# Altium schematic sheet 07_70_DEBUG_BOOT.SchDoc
size 289 x 396 mm
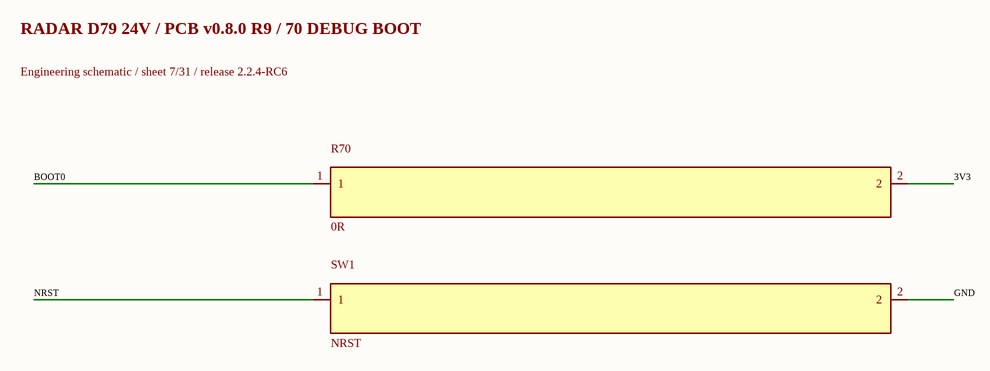
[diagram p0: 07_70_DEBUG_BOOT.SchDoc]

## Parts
R70  0R  [R_0603_1608Metric]
SW1  NRST  [ESwitch_TL3301_GullWing_6x6]

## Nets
3V3: R70.2
BOOT0: R70.1
GND: SW1.2
NRST: SW1.1

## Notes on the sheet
- RADAR D79 24V / PCB v0.8.0 R9 / 70 DEBUG BOOT
- Engineering schematic / sheet 7/31 / release 2.2.4-RC6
